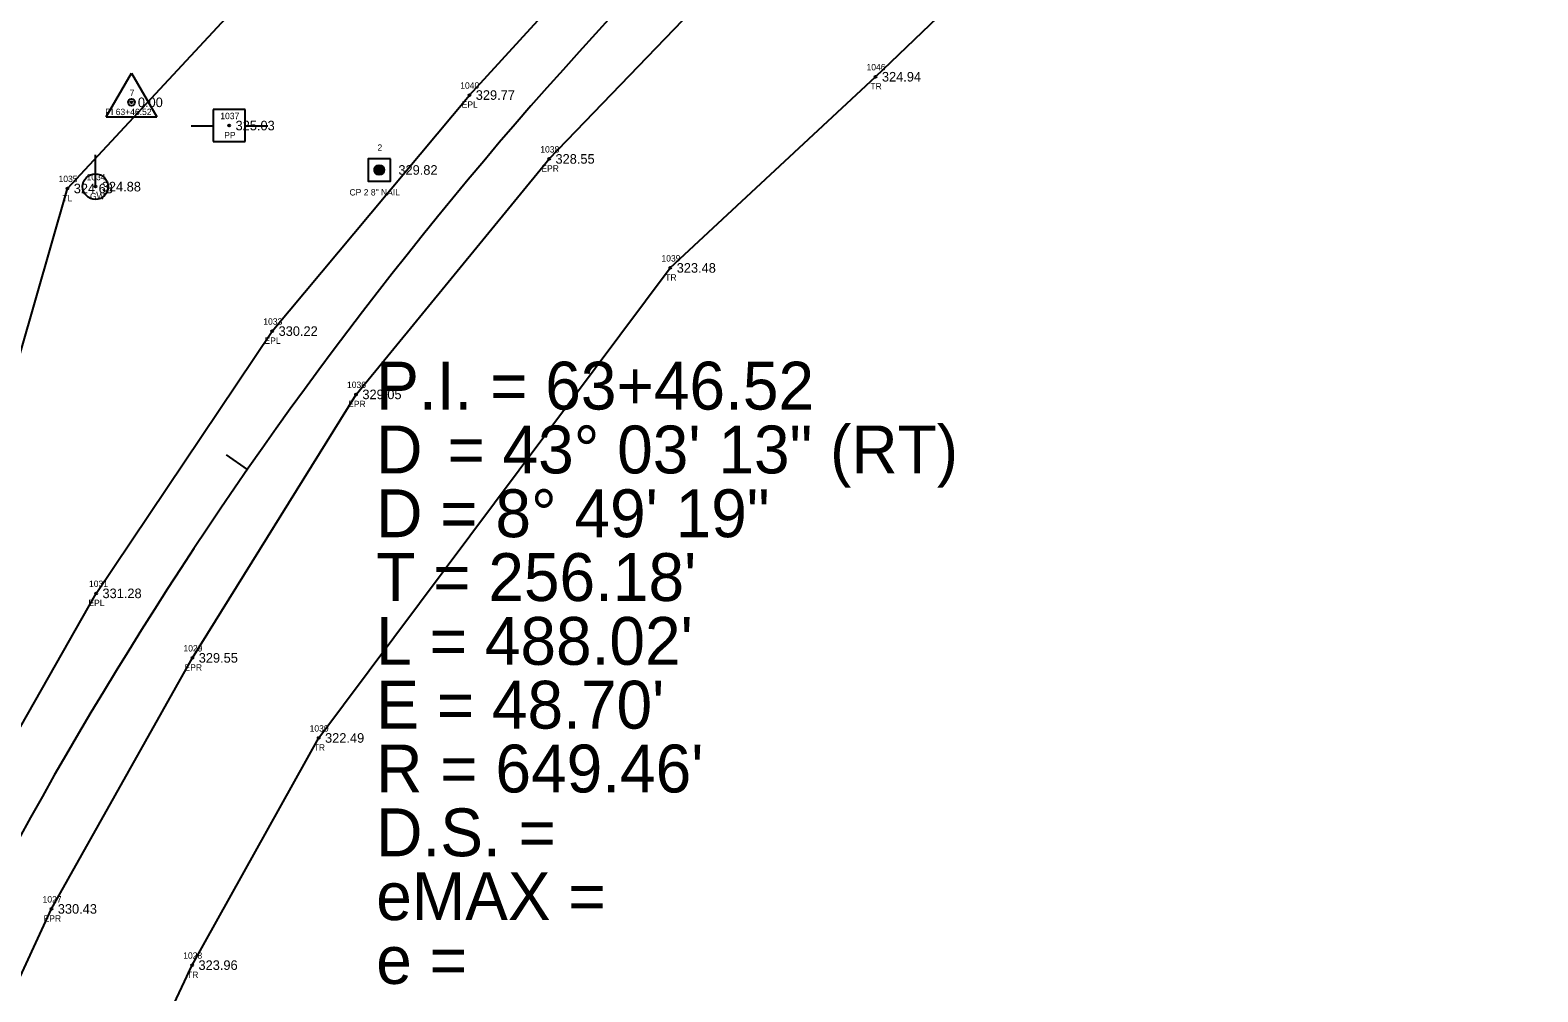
# Model space of a CAD drawing. Extents: x 2231119 to 2232595, y 1035731 to 1037094.
# Drawn here: x 2231312.8 to 2231549, y 1036158.8 to 1036309.5 of the extents above; entities that cross this region are included whole.
import ezdxf

# ---------------------------------------------------------------- set-up
doc = ezdxf.new("R2010")
doc.units = 0
for name, color, linetype in [('RD_EX_Road', 7, 'Continuous'), ('RD_EX_Road_txCode', 7, 'Continuous'), ('RD_EX_TX_Road_ELEV', 7, 'Continuous'), ('RD_EX_TX_UT_ELEV', 7, 'Continuous'), ('RD_EX_TX_VEG_ELEV', 7, 'Continuous'), ('RD_EX_UT', 7, 'Continuous'), ('RD_EX_UT_txCode', 7, 'Continuous'), ('RD_EX_VEG', 7, 'Continuous'), ('RD_EX_VEG_txCode', 7, 'Continuous'), ('RD_HC_Cl', 7, 'Continuous'), ('RD_HC_Data', 7, 'Continuous'), ('RD_HC_Data_Tic', 7, 'Continuous'), ('RD_HC_Survey', 7, 'Continuous'), ('RD_HC_Survey_ELEV', 7, 'Continuous'), ('RD_HC_Survey_txCode', 7, 'Continuous'), ('RD_HC_txCode', 7, 'Continuous'), ('RD_SMD_Locator', 7, 'Continuous')]:
    doc.layers.add(name, color=color, linetype=linetype)

msp = doc.modelspace()

# ---------------------------------------------------------------- linework, layer by layer
at = {"layer": 'RD_EX_Road'}
for points in [[(2231158.42, 1035748.11), (2231188.37, 1035851.38), (2231216.59, 1035946.92), (2231244.77, 1036040.72), (2231278.59, 1036133.31), (2231299.55, 1036179.73), (2231323.11, 1036221.2), (2231350.7, 1036262.3), (2231381.59, 1036299.29), (2231415.97, 1036336.9), (2231452.94, 1036369.74), (2231498.19, 1036405.3), (2231537.2, 1036432.57), (2231541.46, 1036424.96)], [(2231176.43, 1035742.89), (2231206.61, 1035845.83), (2231234.19, 1035940.65), (2231261.92, 1036033.75), (2231294.68, 1036125.28), (2231316.11, 1036171.75), (2231338.19, 1036211.09), (2231363.83, 1036252.38), (2231394.08, 1036289.28), (2231427.67, 1036324.2), (2231464.37, 1036355.5), (2231508.96, 1036392.41), (2231546.55, 1036416.22), (2231541.46, 1036424.96)]]:
    msp.add_lwpolyline(points, dxfattribs=at)
at = {"layer": 'RD_EX_UT'}
for p, q in [((2231346.45, 1036297.01), (2231341.45, 1036297.01)), ((2231341.45, 1036297.01), (2231341.45, 1036292.01)), ((2231346.45, 1036292.01), (2231346.45, 1036297.01)), ((2231338.02, 1036294.45), (2231341.49, 1036294.45)), ((2231346.38, 1036294.45), (2231350.02, 1036294.45)), ((2231341.45, 1036292.01), (2231346.45, 1036292.01)), ((2231323, 1036284.94), (2231323, 1036289.94))]:
    msp.add_line(p, q, dxfattribs=at)
msp.add_circle((2231323, 1036284.94), 2, dxfattribs=at)
at = {"layer": 'RD_EX_VEG'}
for points in [[(2231141.61, 1035753.39), (2231172.54, 1035856.04), (2231200.09, 1035950.41), (2231226.19, 1036046.04), (2231262.9, 1036139.62), (2231281.03, 1036187.82), (2231303.66, 1036232.51), (2231318.61, 1036284.65), (2231353.84, 1036322.59), (2231394.02, 1036358.2), (2231443.85, 1036383.78)], [(2231211.01, 1035732.98), (2231244.87, 1035834.47), (2231267.87, 1035928.24), (2231283.13, 1036029.08), (2231316.25, 1036116.26), (2231338.15, 1036162.94), (2231357.98, 1036198.54), (2231413.07, 1036272.2), (2231445.22, 1036302.16), (2231483.09, 1036338.47), (2231530.02, 1036372.29)]]:
    msp.add_lwpolyline(points, dxfattribs=at)
at = {"layer": 'RD_HC_Cl'}
msp.add_arc((2231880.38, 1035870.33), 649.46, 120.68197, 163.7355, dxfattribs=at)
at = {"layer": 'RD_HC_Data'}
for p, q in [((2231324.69, 1036295.86), (2231328.66, 1036302.74)), ((2231328.66, 1036302.74), (2231332.63, 1036295.86)), ((2231324.69, 1036295.86), (2231332.63, 1036295.86))]:
    msp.add_line(p, q, dxfattribs=at)
msp.add_circle((2231328.66, 1036298.15), 0.529, dxfattribs=at)
at = {"layer": 'RD_HC_Data_Tic'}
msp.add_line((2231346.83, 1036240.62), (2231343.54, 1036242.9), dxfattribs=at)
at = {"layer": 'RD_HC_Survey'}
for p, q in [((2231366.72, 1036287.37), (2231366.72, 1036287.73)), ((2231366.75, 1036287.29), (2231366.75, 1036287.81)), ((2231366.77, 1036287.23), (2231366.77, 1036287.87)), ((2231366.8, 1036287.18), (2231366.8, 1036287.92)), ((2231366.82, 1036287.14), (2231366.82, 1036287.96)), ((2231366.85, 1036287.1), (2231366.85, 1036288)), ((2231366.87, 1036287.07), (2231366.87, 1036288.03)), ((2231366.9, 1036287.04), (2231366.9, 1036288.06)), ((2231366.92, 1036287.01), (2231366.92, 1036288.09)), ((2231366.95, 1036286.99), (2231366.95, 1036288.11)), ((2231366.97, 1036286.97), (2231366.97, 1036288.14)), ((2231367, 1036286.95), (2231367, 1036288.16)), ((2231367.02, 1036286.93), (2231367.02, 1036288.17)), ((2231367.05, 1036286.91), (2231367.05, 1036288.19)), ((2231367.07, 1036286.89), (2231367.07, 1036288.21)), ((2231367.1, 1036286.88), (2231367.1, 1036288.22)), ((2231367.12, 1036286.87), (2231367.12, 1036288.23)), ((2231367.14, 1036286.85), (2231367.14, 1036288.25)), ((2231367.17, 1036286.84), (2231367.17, 1036288.26)), ((2231367.19, 1036286.83), (2231367.19, 1036288.27)), ((2231367.22, 1036286.82), (2231367.22, 1036288.28)), ((2231367.24, 1036286.82), (2231367.24, 1036288.29)), ((2231367.27, 1036286.81), (2231367.27, 1036288.29)), ((2231367.29, 1036286.8), (2231367.29, 1036288.3)), ((2231367.32, 1036286.8), (2231367.32, 1036288.3)), ((2231367.34, 1036286.79), (2231367.34, 1036288.31)), ((2231367.37, 1036286.79), (2231367.37, 1036288.31)), ((2231367.39, 1036286.79), (2231367.39, 1036288.32)), ((2231367.42, 1036286.78), (2231367.42, 1036288.32)), ((2231367.44, 1036286.78), (2231367.44, 1036288.32)), ((2231367.47, 1036286.78), (2231367.47, 1036288.32)), ((2231367.49, 1036286.78), (2231367.49, 1036288.32)), ((2231367.52, 1036286.78), (2231367.52, 1036288.32)), ((2231367.54, 1036286.78), (2231367.54, 1036288.32)), ((2231367.57, 1036286.79), (2231367.57, 1036288.31)), ((2231367.59, 1036286.79), (2231367.59, 1036288.31)), ((2231367.62, 1036286.79), (2231367.62, 1036288.31)), ((2231367.64, 1036286.8), (2231367.64, 1036288.3)), ((2231367.66, 1036286.81), (2231367.66, 1036288.3)), ((2231367.69, 1036286.81), (2231367.69, 1036288.29)), ((2231367.71, 1036286.82), (2231367.71, 1036288.28)), ((2231367.74, 1036286.83), (2231367.74, 1036288.27)), ((2231367.76, 1036286.84), (2231367.76, 1036288.26)), ((2231367.79, 1036286.85), (2231367.79, 1036288.25)), ((2231367.81, 1036286.86), (2231367.81, 1036288.24)), ((2231367.84, 1036286.87), (2231367.84, 1036288.23)), ((2231367.86, 1036286.89), (2231367.86, 1036288.21)), ((2231367.89, 1036286.9), (2231367.89, 1036288.2)), ((2231367.91, 1036286.92), (2231367.91, 1036288.18)), ((2231367.94, 1036286.94), (2231367.94, 1036288.16)), ((2231367.96, 1036286.96), (2231367.96, 1036288.14)), ((2231367.99, 1036286.98), (2231367.99, 1036288.12)), ((2231368.01, 1036287), (2231368.01, 1036288.1)), ((2231368.04, 1036287.03), (2231368.04, 1036288.08)), ((2231368.06, 1036287.05), (2231368.06, 1036288.05)), ((2231368.09, 1036287.09), (2231368.09, 1036288.02)), ((2231368.11, 1036287.12), (2231368.11, 1036287.98)), ((2231368.13, 1036287.16), (2231368.13, 1036287.94)), ((2231368.16, 1036287.2), (2231368.16, 1036287.9)), ((2231368.18, 1036287.26), (2231368.18, 1036287.84)), ((2231368.21, 1036287.33), (2231368.21, 1036287.77)), ((2231368.23, 1036287.44), (2231368.23, 1036287.66))]:
    msp.add_line(p, q, dxfattribs=at)
msp.add_lwpolyline([(2231369.22, 1036289.3), (2231365.72, 1036289.3), (2231365.72, 1036285.8), (2231369.22, 1036285.8)], close=True, dxfattribs=at)
msp.add_circle((2231367.47, 1036287.55), 0.769, dxfattribs=at)
at = {"layer": 'RD_SMD_Locator'}
for centre in [(2231445.22, 1036302.16), (2231328.66, 1036298.15), (2231381.59, 1036299.29), (2231343.96, 1036294.51), (2231394.08, 1036289.28), (2231367.47, 1036287.55), (2231318.61, 1036284.65), (2231323, 1036284.94), (2231413.07, 1036272.2), (2231350.7, 1036262.3), (2231363.83, 1036252.38), (2231323.11, 1036221.2), (2231338.19, 1036211.09), (2231357.98, 1036198.54), (2231316.11, 1036171.75), (2231338.15, 1036162.94)]:
    msp.add_circle(centre, 0.15, dxfattribs=at)

# ---------------------------------------------------------------- texts
at = {"layer": 'RD_EX_Road_txCode'}
for s, p in [('1040', (2231380.16, 1036300.29)), ('EPL', (2231380.38, 1036297.29)), ('1038', (2231392.7, 1036290.28)), ('EPR', (2231392.86, 1036287.28)), ('1033', (2231349.31, 1036263.3)), ('EPL', (2231349.49, 1036260.3)), ('1036', (2231362.42, 1036253.38)), ('EPR', (2231362.6, 1036250.38)), ('1031', (2231322, 1036222.2)), ('EPL', (2231321.9, 1036219.2)), ('1029', (2231336.8, 1036212.09)), ('EPR', (2231336.96, 1036209.09)), ('1027', (2231314.73, 1036172.75)), ('EPR', (2231314.88, 1036169.75))]:
    msp.add_text(s, height=1, dxfattribs=at).set_placement(p)
at = {"layer": 'RD_EX_TX_Road_ELEV'}
for s, p in [('329.77', (2231382.59, 1036298.54)), ('328.55', (2231395.08, 1036288.53)), ('330.22', (2231351.7, 1036261.55)), ('329.05', (2231364.83, 1036251.63)), ('331.28', (2231324.11, 1036220.45)), ('329.55', (2231339.19, 1036210.34)), ('330.43', (2231317.11, 1036171))]:
    msp.add_text(s, height=1.5, dxfattribs=at).set_placement(p)
at = {"layer": 'RD_EX_TX_UT_ELEV'}
msp.add_text('324.88', height=1.5, dxfattribs=at).set_placement((2231324, 1036284.19))
at = {"layer": 'RD_EX_TX_VEG_ELEV'}
for s, p in [('324.94', (2231446.22, 1036301.41)), ('324.68', (2231319.61, 1036283.9)), ('323.48', (2231414.07, 1036271.45)), ('322.49', (2231358.98, 1036197.79)), ('323.96', (2231339.15, 1036162.19))]:
    msp.add_text(s, height=1.5, dxfattribs=at).set_placement(p)
at = {"layer": 'RD_EX_UT_txCode'}
for s, p in [('1037', (2231342.57, 1036295.51)), ('PP', (2231343.18, 1036292.51)), ('1034', (2231321.62, 1036285.94)), ('GW', (2231322.16, 1036282.94))]:
    msp.add_text(s, height=1, dxfattribs=at).set_placement(p)
at = {"layer": 'RD_EX_VEG_txCode'}
for s, p in [('1046', (2231443.81, 1036303.16)), ('TR', (2231444.42, 1036300.16)), ('1035', (2231317.23, 1036285.65)), ('TL', (2231317.84, 1036282.65)), ('1039', (2231411.68, 1036273.2)), ('TR', (2231412.27, 1036270.2)), ('1030', (2231356.56, 1036199.54)), ('TR', (2231357.19, 1036196.54)), ('1028', (2231336.76, 1036163.94)), ('TR', (2231337.35, 1036160.94))]:
    msp.add_text(s, height=1, dxfattribs=at).set_placement(p)
at = {"layer": 'RD_HC_Data'}
for s, p in [('P.I. = 63+46.52', (2231367, 1036250)), ('D', (2231367, 1036240)), ('    = 43%%d 03\' 13" (RT)', (2231367, 1036240)), ('D = 8%%d 49\' 19"', (2231367, 1036230)), ("T = 256.18'", (2231367, 1036220)), ("L = 488.02'", (2231367, 1036210)), ("E = 48.70'", (2231367, 1036200)), ("R = 649.46'", (2231367, 1036190)), ('D.S. = ', (2231367, 1036180)), ('eMAX = ', (2231367, 1036170)), ('e = ', (2231367, 1036160))]:
    msp.add_text(s, height=7.5, dxfattribs=at).set_placement(p)
at = {"layer": 'RD_HC_Survey_ELEV'}
for s, p in [('0.00', (2231329.66, 1036297.4)), ('325.03', (2231344.96, 1036293.76)), ('329.82', (2231370.47, 1036286.8))]:
    msp.add_text(s, height=1.5, dxfattribs=at).set_placement(p)
at = {"layer": 'RD_HC_Survey_txCode'}
for s, p in [('2', (2231367.19, 1036290.55)), ('CP 2 8" NAIL', (2231362.81, 1036283.55))]:
    msp.add_text(s, height=1, dxfattribs=at).set_placement(p)
at = {"layer": 'RD_HC_txCode'}
for s, p in [('7', (2231328.38, 1036299.15)), ('PI 63+46.52', (2231324.55, 1036296.15))]:
    msp.add_text(s, height=1, dxfattribs=at).set_placement(p)

doc.saveas('drawing.dxf')
